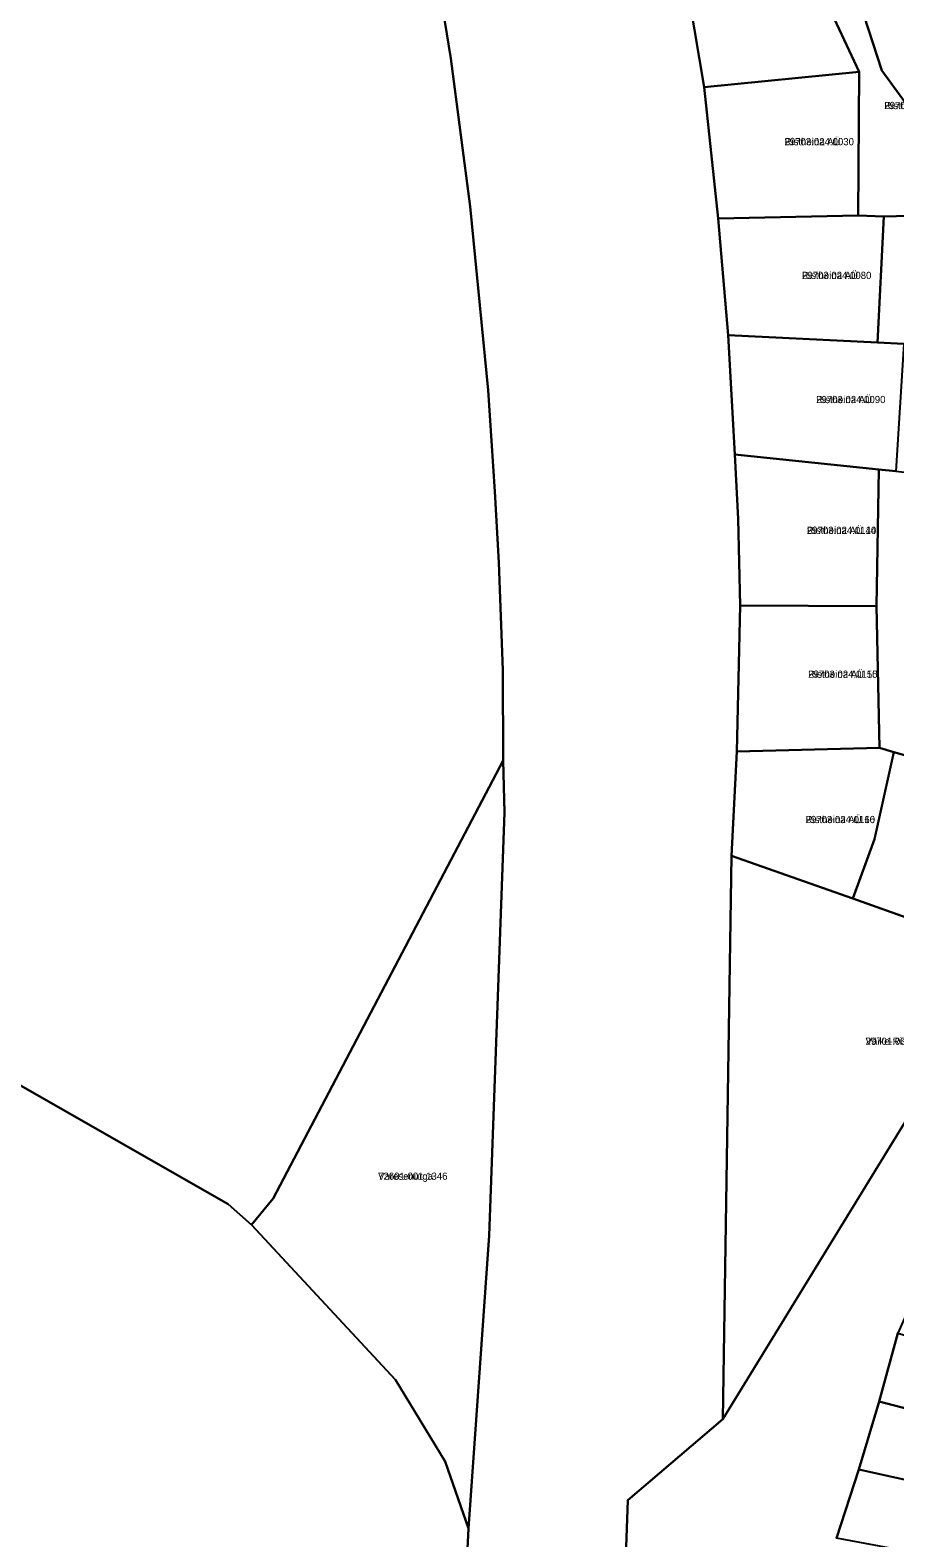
# Model space of a CAD drawing. Extents: x 504287 to 537970, y 6539941 to 6586214.
# Drawn here: x 518245.2 to 518425.8, y 6560795.2 to 6561110.1 of the extents above; entities that cross this region are included whole.
import ezdxf

# ---------------------------------------------------------------- set-up
doc = ezdxf.new("R2010")
doc.units = 0
for name, color, linetype in [('L_AADRESS', 7, 'Continuous'), ('PIIR', 7, 'Continuous'), ('TUNNUS', 7, 'Continuous')]:
    doc.layers.add(name, color=color, linetype=linetype)

msp = doc.modelspace()

# ---------------------------------------------------------------- linework, layer by layer
at = {"layer": 'PIIR'}
for points in [[(518237.31, 6561414.7), (518253.17, 6561379.17), (518265.98, 6561349.39), (518274.98, 6561326.66), (518287.27, 6561292.78), (518295.17, 6561268.96), (518305.11, 6561235.6), (518310.18, 6561216.85), (518317.97, 6561184.9), (518322.56, 6561163.7), (518328.53, 6561132.11), (518333.04, 6561104.15), (518337.1, 6561073.26), (518340.87, 6561034.88), (518342.27, 6561013.71), (518343.1, 6560998.88), (518343.89, 6560976.44), (518344, 6560957.53), (518295.91, 6560866.08), (518291.44, 6560860.56), (518286.54, 6560864.91), (518227.59, 6560898.56)], [(518334.83, 6560757.74), (518336.77, 6560797.14), (518341.07, 6560858.35), (518344.27, 6560946.72), (518344, 6560957.53), (518343.89, 6560976.44), (518343.1, 6560998.88), (518342.27, 6561013.71), (518340.87, 6561034.88), (518337.1, 6561073.26), (518333.04, 6561104.15), (518328.53, 6561132.11), (518322.56, 6561163.7), (518317.97, 6561184.9), (518310.18, 6561216.85), (518305.11, 6561235.6), (518295.17, 6561268.96), (518287.27, 6561292.78), (518274.98, 6561326.66), (518265.98, 6561349.39), (518253.17, 6561379.17), (518237.31, 6561414.7)], [(518306.49, 6561389.32), (518313.48, 6561369.85), (518321.31, 6561348.25), (518328.09, 6561329), (518335.17, 6561308.92), (518342.08, 6561288.28), (518348.41, 6561267.97), (518354.29, 6561247.14), (518361.09, 6561226.69), (518371.34, 6561184.28), (518382.96, 6561115.94), (518386.02, 6561098.18), (518388.9, 6561070.74), (518391.03, 6561046.41), (518392.38, 6561021.45), (518393.11, 6561007.99), (518393.5, 6560989.89), (518392.78, 6560959.41), (518391.7, 6560937.64), (518389.88, 6560820.02), (518370.03, 6560803.08), (518367.07, 6560719.08)], [(518367.07, 6560719.08), (518370.03, 6560803.08), (518389.88, 6560820.02), (518449.53, 6560917.15), (518461.42, 6560947.82), (518470.68, 6560973.62), (518482.91, 6561006.2), (518485.23, 6561012.25), (518493.76, 6561032.39), (518489.05, 6561041.1), (518473.01, 6561072.73), (518470.86, 6561077.26), (518455.39, 6561107.44), (518441.85, 6561134.23), (518429.34, 6561158.7), (518405, 6561224.35), (518399.83, 6561238.56), (518392.11, 6561259.42), (518384.68, 6561279.75), (518377.32, 6561299.82), (518370.28, 6561319.65), (518362.78, 6561339.16), (518355.48, 6561358.99), (518347.39, 6561380.81)], [(518436.08, 6561178.02), (518465.5, 6561108.05), (518502.31, 6561041.16), (518509.02, 6561027.95), (518500.47, 6561014.45), (518495.97, 6561002.88), (518490.99, 6560989.4), (518485.79, 6560975.26), (518480.01, 6560959.92), (518473.78, 6560943.6), (518467.54, 6560926.82), (518460.61, 6560907.64), (518456.81, 6560901.28), (518452.93, 6560890.98), (518446.13, 6560878.53), (518439.78, 6560865.55), (518432.68, 6560851.9), (518426.46, 6560837.98), (518422.54, 6560823.69), (518418.27, 6560809.48), (518413.67, 6560795.15)], [(517952.96, 6560792.25), (517966.89, 6560919.94), (518009.44, 6560961.26), (518018.08, 6560953.8), (518040.59, 6560932.22), (518068.91, 6560907.06), (518076.45, 6560902.41), (518083.42, 6560900.44), (518091.21, 6560900.9), (518106.31, 6560904.92), (518125.02, 6560910.73), (518162.29, 6560917.12), (518172.4, 6560917.36), (518188.9, 6560914.61), (518206.28, 6560909.15), (518215.19, 6560904.96), (518227.59, 6560898.56), (518286.54, 6560864.91), (518291.44, 6560860.56), (518321.53, 6560828.25), (518331.88, 6560811.16), (518336.77, 6560797.14), (518334.83, 6560757.74)]]:
    msp.add_lwpolyline(points, dxfattribs=at)
for points in [[(518382.96, 6561115.94), (518407.93, 6561138.74), (518413.29, 6561132.39), (518412.65, 6561126.32), (518415.12, 6561115.6), (518412.07, 6561114.72), (518418.35, 6561101.35), (518386.02, 6561098.18)], [(518423.12, 6561101.66), (518418.46, 6561115.99), (518441.85, 6561134.23), (518455.39, 6561107.44), (518428.77, 6561093.92)], [(518415.12, 6561115.6), (518418.46, 6561115.99), (518423.12, 6561101.66), (518428.77, 6561093.92), (518435.51, 6561077.76), (518470.86, 6561077.26), (518473.01, 6561072.73), (518452.72, 6561071.95), (518423.5, 6561071.17), (518418.19, 6561071.35), (518418.35, 6561101.35), (518412.07, 6561114.72)], [(518386.02, 6561098.18), (518418.35, 6561101.35), (518418.19, 6561071.35), (518388.9, 6561070.74)], [(518388.9, 6561070.74), (518418.19, 6561071.35), (518423.5, 6561071.17), (518422.18, 6561044.87), (518391.03, 6561046.41)], [(518422.18, 6561044.87), (518423.5, 6561071.17), (518452.72, 6561071.95), (518451.5, 6561043.3), (518427.72, 6561044.55)], [(518391.03, 6561046.41), (518422.18, 6561044.87), (518427.72, 6561044.55), (518426.04, 6561017.97), (518422.49, 6561018.34), (518392.38, 6561021.45)], [(518393.11, 6561007.99), (518392.38, 6561021.45), (518422.49, 6561018.34), (518421.99, 6560989.81), (518393.5, 6560989.89)], [(518426.04, 6561017.97), (518455.48, 6561014.59), (518485.23, 6561012.25), (518482.91, 6561006.2), (518447.04, 6561010.4), (518438.46, 6560985.6), (518427.82, 6560958.68), (518425.62, 6560959.31), (518422.62, 6560960.21), (518421.99, 6560989.81), (518422.49, 6561018.34)], [(518393.5, 6560989.89), (518421.99, 6560989.81), (518422.62, 6560960.21), (518392.78, 6560959.41)], [(518392.78, 6560959.41), (518422.62, 6560960.21), (518425.62, 6560959.31), (518421.58, 6560941.13), (518417.06, 6560928.74), (518391.7, 6560937.64)], [(518336.77, 6560797.14), (518331.88, 6560811.16), (518321.53, 6560828.25), (518291.44, 6560860.56), (518295.91, 6560866.08), (518344, 6560957.53), (518344.27, 6560946.72), (518341.07, 6560858.35)], [(518427.82, 6560958.68), (518461.42, 6560947.82), (518449.53, 6560917.15), (518417.06, 6560928.74), (518421.58, 6560941.13), (518425.62, 6560959.31)], [(518391.7, 6560937.64), (518417.06, 6560928.74), (518449.53, 6560917.15), (518389.88, 6560820.02)], [(518426.46, 6560837.98), (518483.79, 6560821.32), (518479.38, 6560808.88), (518422.54, 6560823.69)], [(518422.54, 6560823.69), (518479.38, 6560808.88), (518475.3, 6560796.89), (518418.27, 6560809.48)], [(518418.27, 6560809.48), (518475.29, 6560796.89), (518472.42, 6560784.26), (518413.67, 6560795.15)]]:
    msp.add_lwpolyline(points, close=True, dxfattribs=at)

# ---------------------------------------------------------------- texts
at = {"layer": 'L_AADRESS'}
for s, p in [('Ristheina üldmaa 1', (518423.61, 6561093.58)), ('Ristheina AÜ 3', (518402.78, 6561086.04)), ('Ristheina AÜ 8', (518406.43, 6561058.11)), ('Ristheina AÜ 9', (518409.37, 6561032.19)), ('Ristheina AÜ 14', (518407.44, 6561004.87)), ('Ristheina AÜ 15', (518407.7, 6560974.83)), ('Ristheina AÜ 16', (518407.18, 6560944.48)), ('Väike-Ristheina', (518419.71, 6560898.19)), ('Varesenurga', (518317.86, 6560870))]:
    msp.add_text(s, height=1.5, dxfattribs=at).set_placement(p)
at = {"layer": 'TUNNUS'}
for s, p in [('29703:024:0001', (518423.61, 6561093.58)), ('29703:024:0030', (518402.78, 6561086.04)), ('29703:024:0080', (518406.43, 6561058.11)), ('29703:024:0090', (518409.37, 6561032.19)), ('29703:024:0140', (518407.44, 6561004.87)), ('29703:024:0150', (518407.7, 6560974.83)), ('29703:024:0160', (518407.18, 6560944.48)), ('29701:001:0698', (518419.71, 6560898.19)), ('72601:001:1346', (518317.86, 6560870))]:
    msp.add_text(s, height=1.5, dxfattribs=at).set_placement(p)

doc.saveas('drawing.dxf')
